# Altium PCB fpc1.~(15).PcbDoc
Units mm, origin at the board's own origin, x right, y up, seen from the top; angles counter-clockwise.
Board outline 92.32 x 7.35 mm, 2 copper layers (Top Layer, Bottom Layer), stack 0.049 mm thick; 4 components, 5 nets, 20 pads, 0 vias.
Unrouted connection lines stored in the file: 3.
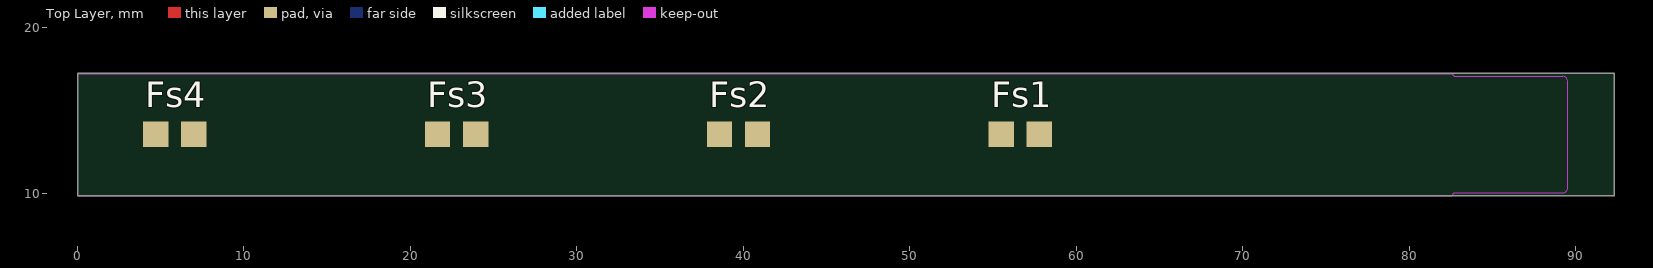
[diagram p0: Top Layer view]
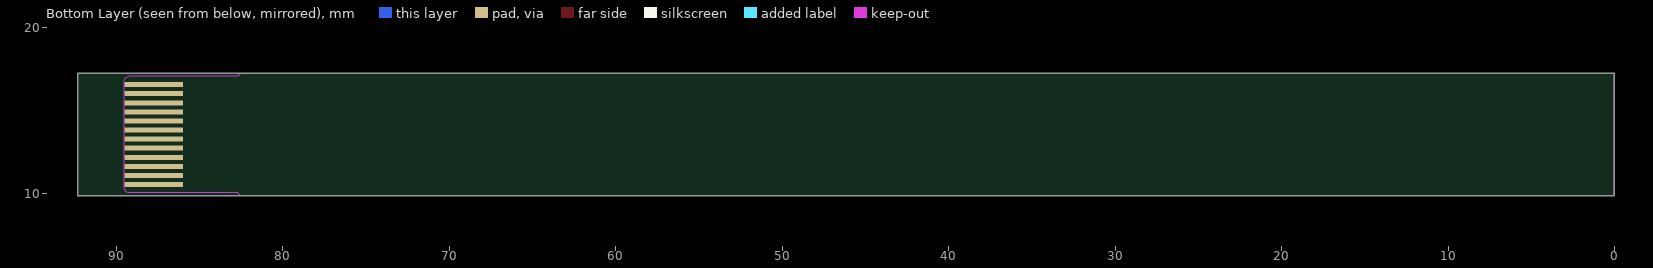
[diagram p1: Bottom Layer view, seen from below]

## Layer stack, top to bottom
Top Solder: solder mask 0.0102, Solder Resist, Dk 3.5
Top Layer: signal copper 0.012
Dielectric 1: dielectric 0.025, FR-4, Dk 4.8
Bottom Layer: signal copper 0.012
Bottom Solder: solder mask 0.0102, Solder Resist, Dk 3.5

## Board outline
0.013,9.887 92.321,9.887 92.328,9.893 92.328,17.226 92.321,17.233 0.013,17.233 0.006,17.226

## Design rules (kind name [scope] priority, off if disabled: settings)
Clearance [All] p1: gap=0.254 ignorepadtopadclearanceinfootprint=FALSE except(0: Arc-Hole Track-Hole SMDPad-Hole THPad-Hole Via-Hole Fill-Hole Poly-Hole Region-Hole Text-Hole)
DiffPairsRouting [All] p1: maxlimit=0.254 minlimit=0.254 mostfreqgap=0.254 toplayer_minwidth=0.381 toplayer_maxwidth=0.381 toplayer_prefwidth=0.381 bottomlayer_minwidth=0.381 bottomlayer_maxwidth=0.381 bottomlayer_prefwidth=0.381 substack1={6BAC4FC8-8DE6-4E41-AF8A-9441F3E19743} toplayer_{6bac4fc8-8de6-4e41-af8a-9441f3e19743}_minwidth=0.381 toplayer_{6bac4fc8-8de6-4e41-af8a-9441f3e19743}_maxwidth=0.381 toplayer_{6bac4fc8-8de6-4e41-af8a-9441f3e19743}_prefwidth=0.381 bottomlayer_{6bac4fc8-8de6-4e41-af8a-9441f3e19743}_minwidth=0.381 bottomlayer_{6bac4fc8-8de6-4e41-af8a-9441f3e19743}_maxwidth=0.381 bottomlayer_{6bac4fc8-8de6-4e41-af8a-9441f3e19743}_prefwidth=0.381 maxuncoupledlength=12.7
PolygonConnect [All] p1: connectstyle=Relief reliefconductorwidth=0.254 reliefentries=4 polygonreliefangle="90 Angle" airgapwidth=0.254
RoutingVias [All] p1: holewidth=0.711 width=1.27 viastyle="Through Hole" minholewidth=0.711 minwidth=1.27 maxholewidth=0.711 maxwidth=1.27
SolderMaskExpansion [All] p1: expansion=0.102 istentingtop=FALSE
Width [All] p1: maxlimit=0.254 minlimit=0.254 preferedwidth=0.254 substack1={6BAC4FC8-8DE6-4E41-AF8A-9441F3E19743}
29 further rules are at their usual default settings.

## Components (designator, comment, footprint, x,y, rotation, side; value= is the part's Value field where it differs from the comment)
Fs1 "ForceSensor" sensor_connector 56.642,13.589 r0 top
Fs2 "ForceSensor" sensor_connector 39.709,13.589 r0 top
Fs3 "ForceSensor" sensor_connector 22.775,13.589 r0 top
Fs4 "ForceSensor" sensor_connector 5.842,13.589 r0 top

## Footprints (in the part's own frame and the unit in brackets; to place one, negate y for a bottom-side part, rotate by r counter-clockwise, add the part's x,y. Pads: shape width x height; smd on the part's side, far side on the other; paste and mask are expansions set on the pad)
sensor_connector [mil]
  rect 60x60 smd: 1(-45,0) 2(45,0)

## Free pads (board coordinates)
  rect 3.5x0.3 smd far side: 3(87.75,10.559) 3(87.75,11.104) 3(87.75,11.65) 3(87.75,12.195) 3(87.75,12.741) 3(87.75,13.286) 3(87.75,13.832) 3(87.75,14.377) 3(87.75,14.923) 3(87.75,15.468) 3(87.75,16.014) 3(87.75,16.559)

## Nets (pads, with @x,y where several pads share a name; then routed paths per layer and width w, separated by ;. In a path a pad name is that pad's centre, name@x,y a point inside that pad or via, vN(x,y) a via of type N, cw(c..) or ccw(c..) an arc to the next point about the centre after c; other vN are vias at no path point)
GND: Fs1.1 Fs2.1 Fs3.1 Fs4.1
NetFs1_0: 
NetFs2_0: 
NetFs3_0: 
NetFs4_0: 
pads on no net: Fs1.2 Fs2.2 Fs3.2 Fs4.2

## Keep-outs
Keep-Out Layer:
  lines w0.013: 0.013,9.893 0.013,17.225 82.547,17.225 82.713,17.059 89.213,17.059 cw(c89.213,16.759) 89.513,16.759 89.513,10.359 cw(c89.213,10.359) 89.213,10.059 82.713,10.059 82.547,9.893 0.013,9.893

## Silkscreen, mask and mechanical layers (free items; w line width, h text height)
Board Shape:
  lines w0.013: 0.013,9.893 0.013,17.225 82.547,17.225 82.713,17.059 89.213,17.059 cw(c89.213,16.759) 89.513,16.759 89.513,10.359 cw(c89.213,10.359) 89.213,10.059 82.713,10.059 82.547,9.893 0.013,9.893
